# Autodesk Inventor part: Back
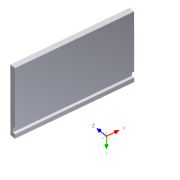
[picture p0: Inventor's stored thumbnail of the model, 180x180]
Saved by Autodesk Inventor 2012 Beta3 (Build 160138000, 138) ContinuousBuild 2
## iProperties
Created: 2011-02
Part Number: Back
Material: Default
Document SubType Name: Modeling
Designer: Beta-8540w
Density: 1 g/cm^3
Author: Beta-8540w
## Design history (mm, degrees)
sketch "Sketch1"
  geometry: L1 (-127, -76.2)-(127, -76.2); L2 (127, -76.2)-(127, 76.2); L3 (127, 76.2)-(-127, 76.2); L4 (-127, 76.2)-(-127, -76.2); 3 further points
  constraints: 8 end point, 2 midpoint, 2 parallel, 1 horizontal, 1 horizontal alignment, 1 perpendicular, 1 vertical alignment
  dimensions: "width" = 254 distance of L3.end L2.end; "height" = 152.4 distance of L2.end L1.end
extrude "Extrusion1" new body sketch "Sketch1" distance "d2" = 12.7; taper "d3" = 0 deg
sketch "Sketch2"
  geometry: L1 (127, -76.2)-(-127, -76.2) reference; L2 (127, 76.2)-(127, -76.2) reference; L3 (-127, -76.2)-(-127, 76.2) reference; L4 (-127, -66.548)-(127, -66.548); L5 (127, -66.548)-(127, -53.848); L6 (127, -53.848)-(-127, -53.848); L7 (-127, -53.848)-(-127, -66.548); 1 further point
  constraints: 8 end point, 2 parallel, 2 point on line, 1 horizontal, 1 perpendicular
  dimensions: "d4" = 9.652 distance between parallel lines of L1 L4; "thickness" = 12.7 distance of L6.end L4.start
extrude "Extrusion2" cut sketch "Sketch2" distance "d6" = 6.35; taper "d7" = 0 deg
body "Solid1"
other parameters: "d20" = 0, "d21" = 0, "offset" = 101.6, "d23" = 0, "d24" = -180 deg, "d25" = -180 deg
